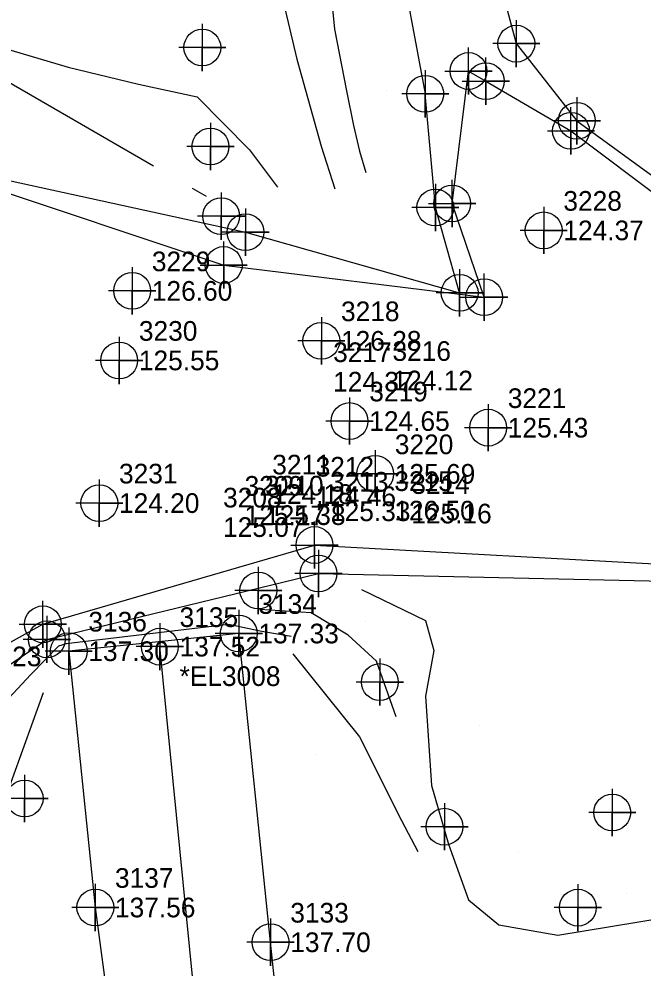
# Model space of a CAD drawing. Extents: x 2312183 to 2312663, y 819676 to 820746.
# Drawn here: x 2312465.5 to 2312544.8, y 820065.9 to 820186.5 of the extents above; entities that cross this region are included whole.
import ezdxf

# ---------------------------------------------------------------- set-up
doc = ezdxf.new("R2010")
doc.units = 0
for name, color, linetype in [('Exist DTM Breakline', 7, 'Continuous'), ('Exist DTM Breakline Cogo Point CELL', 7, 'Continuous'), ('Exist DTM Crownline', 7, 'Continuous'), ('Exist DTM Crownline Cogo Comment', 7, 'Continuous'), ('Exist DTM Crownline Cogo Elevation', 7, 'Continuous'), ('Exist DTM Crownline Cogo Number', 7, 'Continuous'), ('Exist DTM Crownline Cogo Point CELL', 7, 'Continuous'), ('Exist DTM Regular Point CELL', 7, 'Continuous'), ('Exist DTM Regular Point Cogo Elevation', 7, 'Continuous'), ('Exist DTM Regular Point Cogo Number', 7, 'Continuous'), ('Exist DTM Regular Point Underwater CELL', 7, 'Continuous'), ('Exist DTM Regular Point Underwater Cogo Elevation', 7, 'Continuous'), ('Exist DTM Regular Point Underwater Cogo Number', 7, 'Continuous'), ('Exist Hydro Stream or Body of Water', 7, 'Continuous'), ('Exist Hydro Stream or Body of Water Cogo Point CELL', 7, 'Continuous'), ('Exist Roads EOP', 7, 'Continuous'), ('Exist Roads EOP Cogo Elevation', 7, 'Continuous'), ('Exist Roads EOP Cogo Number', 7, 'Continuous'), ('Exist Roads EOP Cogo Point CELL', 7, 'Continuous'), ('PH Exist DTM Breakline', 7, 'Continuous'), ('PH Exist DTM Point', 7, 'Continuous')]:
    doc.layers.add(name, color=color, linetype=linetype)

msp = doc.modelspace()

# ---------------------------------------------------------------- linework, layer by layer
at = {"layer": 'Exist DTM Breakline'}
for points in [[(2312522.1, 820208.19), (2312528.71, 820183.41), (2312536.41, 820173.61), (2312549.61, 820163.99)], [(2312513.35, 820197.24), (2312517.14, 820177.02)], [(2312453.92, 820175.89), (2312460.54, 820166.81), (2312494.29, 820159.45), (2312521.51, 820151.72), (2312518.42, 820162.59), (2312517.14, 820177.02)], [(2312469.05, 820107.68), (2312503.56, 820116.05), (2312551.33, 820115), (2312576, 820099.16)], [(2312398.6, 820034.89), (2312415.76, 820055.03), (2312429.05, 820071.99), (2312440.81, 820088.6), (2312469.05, 820107.68)]]:
    msp.add_lwpolyline(points, dxfattribs=at)
at = {"layer": 'Exist DTM Breakline Cogo Point CELL'}
for points in [[(2312528.71, 820186.41), (2312528.71, 820180.41), (2312528.71, 820183.41), (2312531.71, 820183.41), (2312525.71, 820183.41)], [(2312517.14, 820180.02), (2312517.14, 820174.02), (2312517.14, 820177.02), (2312520.14, 820177.02), (2312514.14, 820177.02)], [(2312536.41, 820176.61), (2312536.41, 820170.61), (2312536.41, 820173.61), (2312539.41, 820173.61), (2312533.41, 820173.61)], [(2312518.42, 820165.59), (2312518.42, 820159.59), (2312518.42, 820162.59), (2312521.42, 820162.59), (2312515.42, 820162.59)], [(2312494.29, 820162.45), (2312494.29, 820156.45), (2312494.29, 820159.45), (2312497.29, 820159.45), (2312491.29, 820159.45)], [(2312521.51, 820154.72), (2312521.51, 820148.72), (2312521.51, 820151.72), (2312524.51, 820151.72), (2312518.51, 820151.72)], [(2312503.56, 820119.05), (2312503.56, 820113.05), (2312503.56, 820116.05), (2312506.56, 820116.05), (2312500.56, 820116.05)], [(2312469.05, 820110.68), (2312469.05, 820104.68), (2312469.05, 820107.68), (2312472.05, 820107.68), (2312466.05, 820107.68)]]:
    msp.add_lwpolyline(points, dxfattribs=at)
for centre in [(2312528.71, 820183.41), (2312517.14, 820177.02), (2312536.41, 820173.61), (2312518.42, 820162.59), (2312494.29, 820159.45), (2312521.51, 820151.72), (2312503.56, 820116.05), (2312469.05, 820107.68)]:
    msp.add_circle(centre, 2.34, dxfattribs=at)
at = {"layer": 'Exist DTM Crownline'}
msp.add_lwpolyline([(2312507.73, 819871.39), (2312502.62, 819916.87), (2312496.97, 819970.94), (2312491.86, 820021.16), (2312483.41, 820106.75)], dxfattribs=at)
at = {"layer": 'Exist DTM Crownline Cogo Point CELL'}
msp.add_lwpolyline([(2312483.41, 820109.75), (2312483.41, 820103.75), (2312483.41, 820106.75), (2312486.41, 820106.75), (2312480.41, 820106.75)], dxfattribs=at)
msp.add_lwpolyline([(2312483.41, 820109.75), (2312483.41, 820103.75), (2312483.41, 820106.75), (2312486.41, 820106.75), (2312480.41, 820106.75)], dxfattribs=at)
msp.add_circle((2312483.41, 820106.75), 2.34, dxfattribs=at)
msp.add_circle((2312483.41, 820106.75), 2.34, dxfattribs=at)
at = {"layer": 'Exist DTM Regular Point CELL'}
for points in [[(2312488.8, 820185.91), (2312488.8, 820179.91), (2312488.8, 820182.91), (2312491.8, 820182.91), (2312485.8, 820182.91)], [(2312489.83, 820173.33), (2312489.83, 820167.33), (2312489.83, 820170.33), (2312492.83, 820170.33), (2312486.83, 820170.33)], [(2312491.2, 820164.49), (2312491.2, 820158.49), (2312491.2, 820161.49), (2312494.2, 820161.49), (2312488.2, 820161.49)], [(2312495.92, 820116.89), (2312495.92, 820110.89), (2312495.92, 820113.89), (2312498.92, 820113.89), (2312492.92, 820113.89)], [(2312511.36, 820105.25), (2312511.36, 820099.25), (2312511.36, 820102.25), (2312514.36, 820102.25), (2312508.36, 820102.25)], [(2312466.22, 820090.45), (2312466.22, 820084.45), (2312466.22, 820087.45), (2312469.22, 820087.45), (2312463.22, 820087.45)], [(2312540.91, 820088.67), (2312540.91, 820082.67), (2312540.91, 820085.67), (2312543.91, 820085.67), (2312537.91, 820085.67)], [(2312519.58, 820086.86), (2312519.58, 820080.86), (2312519.58, 820083.86), (2312522.58, 820083.86), (2312516.58, 820083.86)], [(2312536.54, 820076.57), (2312536.54, 820070.57), (2312536.54, 820073.57), (2312539.54, 820073.57), (2312533.54, 820073.57)]]:
    msp.add_lwpolyline(points, dxfattribs=at)
for centre in [(2312488.8, 820182.91), (2312489.83, 820170.33), (2312491.2, 820161.49), (2312495.92, 820113.89), (2312511.36, 820102.25), (2312466.22, 820087.45), (2312540.91, 820085.67), (2312519.58, 820083.86), (2312536.54, 820073.57)]:
    msp.add_circle(centre, 2.34, dxfattribs=at)
at = {"layer": 'Exist DTM Regular Point Underwater CELL'}
for points in [[(2312532.19, 820162.67), (2312532.19, 820156.67), (2312532.19, 820159.67), (2312535.19, 820159.67), (2312529.19, 820159.67)], [(2312479.89, 820154.98), (2312479.89, 820148.98), (2312479.89, 820151.98), (2312482.89, 820151.98), (2312476.89, 820151.98)], [(2312503.93, 820148.63), (2312503.93, 820142.63), (2312503.93, 820145.63), (2312506.93, 820145.63), (2312500.93, 820145.63)], [(2312478.24, 820146.14), (2312478.24, 820140.14), (2312478.24, 820143.14), (2312481.24, 820143.14), (2312475.24, 820143.14)], [(2312507.52, 820138.43), (2312507.52, 820132.43), (2312507.52, 820135.43), (2312510.52, 820135.43), (2312504.52, 820135.43)], [(2312525.13, 820137.59), (2312525.13, 820131.59), (2312525.13, 820134.59), (2312528.13, 820134.59), (2312522.13, 820134.59)], [(2312510.77, 820131.72), (2312510.77, 820125.72), (2312510.77, 820128.72), (2312513.77, 820128.72), (2312507.77, 820128.72)], [(2312475.71, 820128), (2312475.71, 820122), (2312475.71, 820125), (2312478.71, 820125), (2312472.71, 820125)]]:
    msp.add_lwpolyline(points, dxfattribs=at)
for centre in [(2312532.19, 820159.67), (2312479.89, 820151.98), (2312503.93, 820145.63), (2312478.24, 820143.14), (2312507.52, 820135.43), (2312525.13, 820134.59), (2312510.77, 820128.72), (2312475.71, 820125)]:
    msp.add_circle(centre, 2.34, dxfattribs=at)
at = {"layer": 'Exist Hydro Stream or Body of Water'}
for points in [[(2312451.58, 820173.11), (2312459.27, 820166.01), (2312491.52, 820155.27), (2312524.63, 820151.17), (2312520.55, 820163.08), (2312522.64, 820179.93)], [(2312522.64, 820179.93), (2312524.84, 820178.65)], [(2312524.84, 820178.65), (2312535.66, 820172.32), (2312547.88, 820163.13)], [(2312393.18, 820036.93), (2312414.57, 820059.59), (2312427.23, 820072.7), (2312438.05, 820092.67), (2312468.54, 820109.59), (2312503.07, 820119.67), (2312550.88, 820117.01)]]:
    msp.add_lwpolyline(points, dxfattribs=at)
at = {"layer": 'Exist Hydro Stream or Body of Water Cogo Point CELL'}
for points in [[(2312519.64, 820179.93), (2312525.64, 820179.93), (2312522.64, 820179.93), (2312522.64, 820176.93), (2312522.64, 820182.93)], [(2312521.84, 820178.65), (2312527.84, 820178.65), (2312524.84, 820178.65), (2312524.84, 820175.65), (2312524.84, 820181.65)], [(2312532.66, 820172.32), (2312538.66, 820172.32), (2312535.66, 820172.32), (2312535.66, 820169.32), (2312535.66, 820175.32)], [(2312517.55, 820163.08), (2312523.55, 820163.08), (2312520.55, 820163.08), (2312520.55, 820160.08), (2312520.55, 820166.08)], [(2312488.52, 820155.27), (2312494.52, 820155.27), (2312491.52, 820155.27), (2312491.52, 820152.27), (2312491.52, 820158.27)], [(2312521.63, 820151.17), (2312527.63, 820151.17), (2312524.63, 820151.17), (2312524.63, 820148.17), (2312524.63, 820154.17)], [(2312500.07, 820119.67), (2312506.07, 820119.67), (2312503.07, 820119.67), (2312503.07, 820116.67), (2312503.07, 820122.67)], [(2312465.54, 820109.59), (2312471.54, 820109.59), (2312468.54, 820109.59), (2312468.54, 820106.59), (2312468.54, 820112.59)]]:
    msp.add_lwpolyline(points, dxfattribs=at)
for centre in [(2312522.64, 820179.93), (2312524.84, 820178.65), (2312535.66, 820172.32), (2312520.55, 820163.08), (2312491.52, 820155.27), (2312524.63, 820151.17), (2312503.07, 820119.67), (2312468.54, 820109.59)]:
    msp.add_circle(centre, 2.34, dxfattribs=at)
at = {"layer": 'Exist Roads EOP'}
msp.add_lwpolyline([(2312518.41, 819872.35), (2312513.32, 819920.69), (2312507.89, 819970.07), (2312502.32, 820023.24), (2312497.48, 820069.17), (2312493.43, 820108.42), (2312471.82, 820106.17), (2312475.2, 820073.59), (2312480.64, 820032.66), (2312484.77, 819994.6), (2312489.93, 819944.86), (2312494.64, 819899.39), (2312498.09, 819869.36)], dxfattribs=at)
at = {"layer": 'Exist Roads EOP Cogo Point CELL'}
for points in [[(2312493.43, 820111.42), (2312493.43, 820105.42), (2312493.43, 820108.42), (2312496.43, 820108.42), (2312490.43, 820108.42)], [(2312493.43, 820111.42), (2312493.43, 820105.42), (2312493.43, 820108.42), (2312496.43, 820108.42), (2312490.43, 820108.42)], [(2312493.43, 820111.42), (2312493.43, 820105.42), (2312493.43, 820108.42), (2312496.43, 820108.42), (2312490.43, 820108.42)], [(2312471.82, 820109.17), (2312471.82, 820103.17), (2312471.82, 820106.17), (2312474.82, 820106.17), (2312468.82, 820106.17)], [(2312471.82, 820109.17), (2312471.82, 820103.17), (2312471.82, 820106.17), (2312474.82, 820106.17), (2312468.82, 820106.17)], [(2312471.82, 820109.17), (2312471.82, 820103.17), (2312471.82, 820106.17), (2312474.82, 820106.17), (2312468.82, 820106.17)], [(2312475.2, 820076.59), (2312475.2, 820070.59), (2312475.2, 820073.59), (2312478.2, 820073.59), (2312472.2, 820073.59)], [(2312475.2, 820076.59), (2312475.2, 820070.59), (2312475.2, 820073.59), (2312478.2, 820073.59), (2312472.2, 820073.59)], [(2312475.2, 820076.59), (2312475.2, 820070.59), (2312475.2, 820073.59), (2312478.2, 820073.59), (2312472.2, 820073.59)], [(2312497.48, 820072.17), (2312497.48, 820066.17), (2312497.48, 820069.17), (2312500.48, 820069.17), (2312494.48, 820069.17)], [(2312497.48, 820072.17), (2312497.48, 820066.17), (2312497.48, 820069.17), (2312500.48, 820069.17), (2312494.48, 820069.17)], [(2312497.48, 820072.17), (2312497.48, 820066.17), (2312497.48, 820069.17), (2312500.48, 820069.17), (2312494.48, 820069.17)]]:
    msp.add_lwpolyline(points, dxfattribs=at)
for centre in [(2312493.43, 820108.42), (2312493.43, 820108.42), (2312493.43, 820108.42), (2312471.82, 820106.17), (2312471.82, 820106.17), (2312471.82, 820106.17), (2312475.2, 820073.59), (2312475.2, 820073.59), (2312475.2, 820073.59), (2312497.48, 820069.17), (2312497.48, 820069.17), (2312497.48, 820069.17)]:
    msp.add_circle(centre, 2.34, dxfattribs=at)
at = {"layer": 'PH Exist DTM Breakline'}
for points in [[(2312504.65, 820214.85), (2312504.97, 820204.97), (2312505.33, 820197.71), (2312504.97, 820191.78), (2312505.62, 820185.27), (2312507.11, 820177.43), (2312508, 820173.01), (2312508.77, 820169.75), (2312509.59, 820167.04)], [(2312496.98, 820211.89), (2312497.58, 820200.8), (2312498.01, 820193.29), (2312500.8, 820181.42), (2312503.91, 820170.36), (2312505.64, 820164.97)], [(2312443.92, 820193.42), (2312449.14, 820189.59), (2312458.71, 820184.29), (2312471.76, 820180.42), (2312480.71, 820178.26), (2312488.13, 820176.64), (2312494.81, 820169.91), (2312498.34, 820165.17)], [(2312462.34, 820179.59), (2312482.6, 820167.87)], [(2312487.53, 820165.02), (2312489.28, 820164)], [(2312509.03, 820114.01), (2312517.15, 820110.06), (2312518.21, 820106.25), (2312517.15, 820100.47), (2312517.95, 820089.08), (2312520.08, 820081.64), (2312522.64, 820074.56), (2312526.51, 820071.39), (2312534, 820070.09), (2312547.61, 820072.32), (2312559.01, 820061.03), (2312567.96, 820052.87), (2312577.86, 820050.42), (2312591.06, 820050.01), (2312604.11, 820048.43), (2312614.06, 820045.26), (2312625.22, 820040.28), (2312636.84, 820030.53), (2312642.68, 820027.68), (2312652.67, 820025.8), (2312662.18, 820024.81)], [(2312513.43, 820097.82), (2312510.92, 820104.92), (2312507.35, 820108.22), (2312502.65, 820111.05), (2312496.05, 820111.48)], [(2312500.08, 820108.06), (2312496.36, 820108.67), (2312492.14, 820109.57), (2312471.51, 820107.11), (2312470.52, 820106.81), (2312467.01, 820103.19), (2312463.02, 820098.96)], [(2312500.31, 820105.84), (2312508.8, 820095.3), (2312514.11, 820084.66), (2312516.18, 820080.7)], [(2312468.58, 820100.89), (2312463.34, 820086.29), (2312460.04, 820080.12), (2312456.79, 820073.77), (2312457.87, 820064.19), (2312460.28, 820052.1), (2312461.5, 820043.97), (2312462.94, 820036.24), (2312464.44, 820024.72), (2312467.71, 820007.01), (2312471.31, 819991.07), (2312472.67, 819975.28), (2312474.3, 819960.8), (2312475.94, 819945.72), (2312478.04, 819932.21)]]:
    msp.add_lwpolyline(points, dxfattribs=at)
at = {"layer": 'PH Exist DTM Point'}
for p, q in [((2312512.27, 820177.47), (2312512.27, 820177.47)), ((2312509.57, 820109.99), (2312509.57, 820109.99)), ((2312524.08, 820096.75), (2312524.08, 820096.75)), ((2312503.34, 820092.99), (2312503.34, 820092.99)), ((2312528.98, 820080.56), (2312528.98, 820080.56)), ((2312506.74, 820074.94), (2312506.74, 820074.94)), ((2312542.73, 820075.36), (2312542.73, 820075.36))]:
    msp.add_line(p, q, dxfattribs=at)

# ---------------------------------------------------------------- texts
at = {"layer": 'Exist DTM Crownline Cogo Comment'}
msp.add_text('*EL3008', height=2.5, dxfattribs=at).set_placement((2312485.91, 820101.75))
at = {"layer": 'Exist DTM Crownline Cogo Elevation'}
msp.add_text('137.52', height=2.5, dxfattribs=at).set_placement((2312485.91, 820105.5))
at = {"layer": 'Exist DTM Crownline Cogo Number'}
msp.add_text('3135', height=2.5, dxfattribs=at).set_placement((2312485.91, 820109.25))
at = {"layer": 'Exist DTM Regular Point Cogo Elevation'}
for s, p in [('124.37', (2312505.43, 820139.18)), ('124.12', (2312512.97, 820139.33)), ('124.18', (2312497.69, 820124.89)), ('124.46', (2312503.2, 820124.62)), ('125.33', (2312505.03, 820122.71)), ('126.50', (2312513.2, 820122.79)), ('125.17', (2312494.18, 820122.19)), ('125.38', (2312496.78, 820122.22)), ('125.16', (2312515.36, 820122.42)), ('125.07', (2312491.44, 820120.7))]:
    msp.add_text(s, height=2.5, dxfattribs=at).set_placement(p)
at = {"layer": 'Exist DTM Regular Point Cogo Number'}
for s, p in [('3216', (2312512.97, 820143.08)), ('3217', (2312505.43, 820142.93)), ('3211', (2312497.69, 820128.64)), ('3212', (2312503.2, 820128.37)), ('3213', (2312505.03, 820126.46)), ('3215', (2312513.2, 820126.54)), ('3214', (2312515.36, 820126.17)), ('3209', (2312494.18, 820125.94)), ('3210', (2312496.78, 820125.97)), ('3208', (2312491.44, 820124.45))]:
    msp.add_text(s, height=2.5, dxfattribs=at).set_placement(p)
at = {"layer": 'Exist DTM Regular Point Underwater Cogo Elevation'}
for s, p in [('124.37', (2312534.69, 820158.42)), ('126.60', (2312482.39, 820150.73)), ('126.28', (2312506.43, 820144.38)), ('125.55', (2312480.74, 820141.89)), ('124.65', (2312510.02, 820134.18)), ('125.43', (2312527.63, 820133.34)), ('125.69', (2312513.27, 820127.47)), ('124.20', (2312478.21, 820123.75)), ('126.23', (2312458.13, 820104.26))]:
    msp.add_text(s, height=2.5, dxfattribs=at).set_placement(p)
at = {"layer": 'Exist DTM Regular Point Underwater Cogo Number'}
for s, p in [('3228', (2312534.69, 820162.17)), ('3229', (2312482.39, 820154.48)), ('3218', (2312506.43, 820148.13)), ('3230', (2312480.74, 820145.64)), ('3219', (2312510.02, 820137.93)), ('3221', (2312527.63, 820137.09)), ('3220', (2312513.27, 820131.22)), ('3231', (2312478.21, 820127.5))]:
    msp.add_text(s, height=2.5, dxfattribs=at).set_placement(p)
at = {"layer": 'Exist Roads EOP Cogo Elevation'}
for s, p in [('137.33', (2312495.93, 820107.17)), ('137.30', (2312474.32, 820104.92)), ('137.56', (2312477.7, 820072.34)), ('137.70', (2312499.98, 820067.92))]:
    msp.add_text(s, height=2.5, dxfattribs=at).set_placement(p)
at = {"layer": 'Exist Roads EOP Cogo Number'}
for s, p in [('3134', (2312495.93, 820110.92)), ('3136', (2312474.32, 820108.67)), ('3137', (2312477.7, 820076.09)), ('3133', (2312499.98, 820071.67))]:
    msp.add_text(s, height=2.5, dxfattribs=at).set_placement(p)

doc.saveas('drawing.dxf')
